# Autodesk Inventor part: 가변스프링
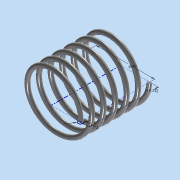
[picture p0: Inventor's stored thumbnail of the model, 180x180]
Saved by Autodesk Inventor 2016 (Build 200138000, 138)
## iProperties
Created: 2018-02
Part Number: 가변스프링
Material: 스테인레스 스틸
Document SubType Name: Modeling
Designer: 605-07
Density: 8 g/cm^3
Appearance: 반연마
Mass: 42.0347 g
Surface Area: 70.9096 cm^2
Volume: 5.25434 cm^3
Author: 605-07
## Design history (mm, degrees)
sketch "스케치1"
  geometry: L1 (0, 0)-(20, 0); L2 (20, 0)-(20, 47.25); L3 (20, 47.25)-(0, 47.25); L4 (0, 47.25)-(0, 0); C1 r 1.5 at (20, 0)
  constraints: 8 end point, 2 parallel, 1 centre point, 1 coincident, 1 horizontal, 1 perpendicular
  dimensions: "d0" = 3 diameter of C1; "d1" = 40 diameter of L2 L4; "d2" = 47.25 distance of L1.end L2.end (derived)
feature "코일1" sketch "스케치1" pitch "d3" = 10; turns "d5" = 6; dims "d4" = 47.25 (= d2), "d6" = 0, angle "d7" = 90 deg, angle "d8" = 90 deg, "d9" = 0, "d10" = 0
sketch "스케치2"
  geometry: L1 (-18.5, 0)-(-21.5, 0) reference; 1 further point
  constraints: 1 horizontal alignment
extrude "돌출1" cut sketch "스케치2" distance "d11" = 10; taper "d12" = 0 deg
node "작업 평면1"
sketch "스케치3"
  geometry: L1 (-1.5, 0)-(1.5, 0) reference; 1 further point
  constraints: 1 horizontal alignment
extrude "돌출2" cut sketch "스케치3" distance "d14" = 10; taper "d15" = 0 deg
node "솔리드1"
node "절단 모서리 투영1"
node "절단 모서리 투영2"
other parameters: "d13" = 90 deg
